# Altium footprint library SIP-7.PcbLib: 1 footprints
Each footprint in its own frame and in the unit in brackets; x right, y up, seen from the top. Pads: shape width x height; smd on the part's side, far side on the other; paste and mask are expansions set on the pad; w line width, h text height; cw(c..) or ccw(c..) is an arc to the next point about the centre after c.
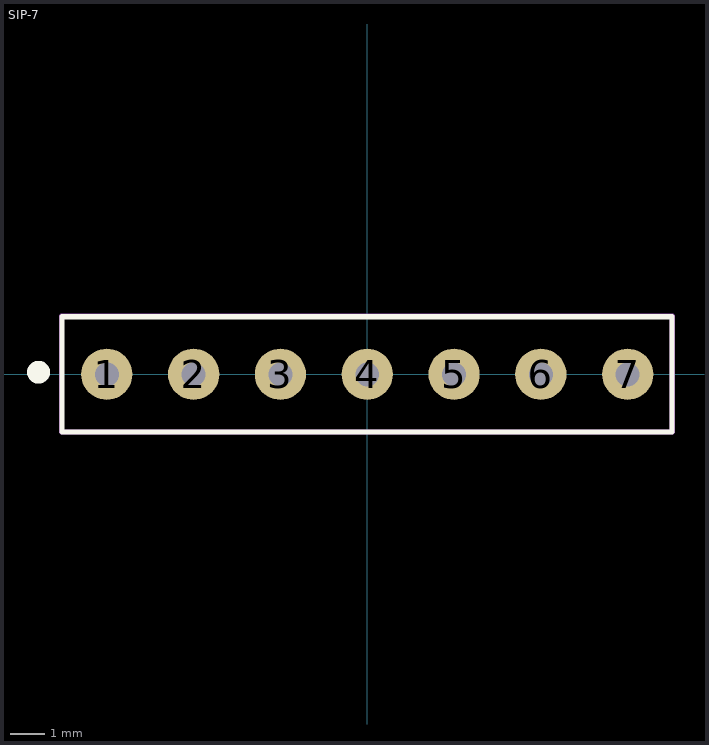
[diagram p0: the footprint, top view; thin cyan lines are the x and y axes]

## SIP-7 [mm]
pads (7):
  round 1.5 hole 0.7: 1(-7.62,0) 2(-5.08,0) 3(-2.54,0) 4(0,0) 5(2.54,0) 6(5.08,0) 7(7.62,0)
Top Overlay:
  circle w0.508: c-9.618,0.06 r0.079
  lines w0.152: -8.935,-1.686 8.917,-1.686 8.917,1.686 -8.935,1.686 -8.935,-1.686
Mechanical 15:
  lines w0.152: -8.946,-1.686 -8.946,1.703 8.922,1.703 8.922,-1.686 -8.946,-1.686
3D body: height 6.6, standoff 0, extent -8.932,-1.656 8.928,1.692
